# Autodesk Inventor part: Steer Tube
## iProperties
Shininess: 64.0
Length Units: 11272
Angle Units: 11279
Time Units: 11290
Mass Units: 11283
Length Display Precision: 3
Angle Display Precision: 2
Compacted: True
Part Number: Steer Tube
Document SubType Name: Modeling
Created: 2005-03
Designer: Admin
Manufacturer: Standard
Standards Organization: Custom
Density: 1 g/cm^3
Density: 0.0
Volumn: 0.0
Area: 0.0
PropertySet Name: Model Information
Control State: 0
Master: False
Checked Out: False
Author: Admin
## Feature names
1. ExtrusionBlind1
2. Hole1
3. Chamfer1
4. Chamfer2
